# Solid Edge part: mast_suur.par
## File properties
Author: kaisa
Template: Iso Metric Part.par
Last saved by: kaisa
Revision: 4
Application: Solid Edge
Accuracy: 0.990
Username: kaisa
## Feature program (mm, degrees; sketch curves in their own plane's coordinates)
sketch for "unnamed RevolvedProtrusion 1" plane through (0, 0, 0) normal (1, 0, 0) x-axis (0, 1, 0)
  line (3, 250) -> (3, 0)
  line (3, 0) -> (0, 0)
  line (0, 0) -> (0, 250)
  line (0, 250) -> (3, 250)
revolve "unnamed RevolvedProtrusion 1" add finite 360 deg
sketch for "unnamed RevolvedProtrusion 2" plane through (-5, 0, 0) normal (1, 0, 0) x-axis (0, 1, 0)
  line (-100, 164.5646) -> (100, 164.5646)
  line (100, 162.8979) -> (100, 164.5646)
  line (-100, 162.8979) -> (100, 162.8979)
  line (-100, 164.5646) -> (-100, 162.8979)
revolve "unnamed RevolvedProtrusion 2" add finite 360 deg
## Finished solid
Body 1: solid body, 6 faces, 4 edges, 0 vertices, 2 separate solids.
  Faces by surface: plane 4, cylinder 2
  Edges by curve: circle 4
Bounding box of the edges (mm): 9.667 x 200.000 x 250.000, from (-6.6667, -100, 0) to (3, 100, 250).
Cylindrical faces by radius (mm): R1.6667 x1, R3 x1
Planar faces by outward normal: +y 1, +z 1, -y 1, -z 1
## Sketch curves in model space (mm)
line (-5, 100, 162.8979) -> (-5, 100, 164.5646)
line (-5, -100, 162.8979) -> (-5, 100, 162.8979)
line (-5, -100, 164.5646) -> (-5, -100, 162.8979)
line (-5, -100, 164.5646) -> (-5, 100, 164.5646)
line (0, 0, 250) -> (0, 3, 250)
line (0, 3, 250) -> (0, 3, 0)
line (0, 3, 0) -> (0, 0, 0)
line (0, 0, 0) -> (0, 0, 250)
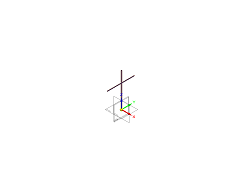
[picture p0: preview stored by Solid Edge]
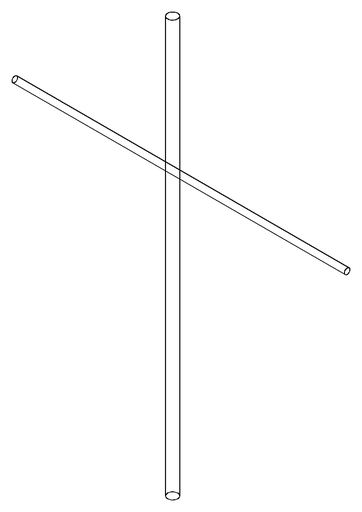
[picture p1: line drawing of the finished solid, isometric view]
